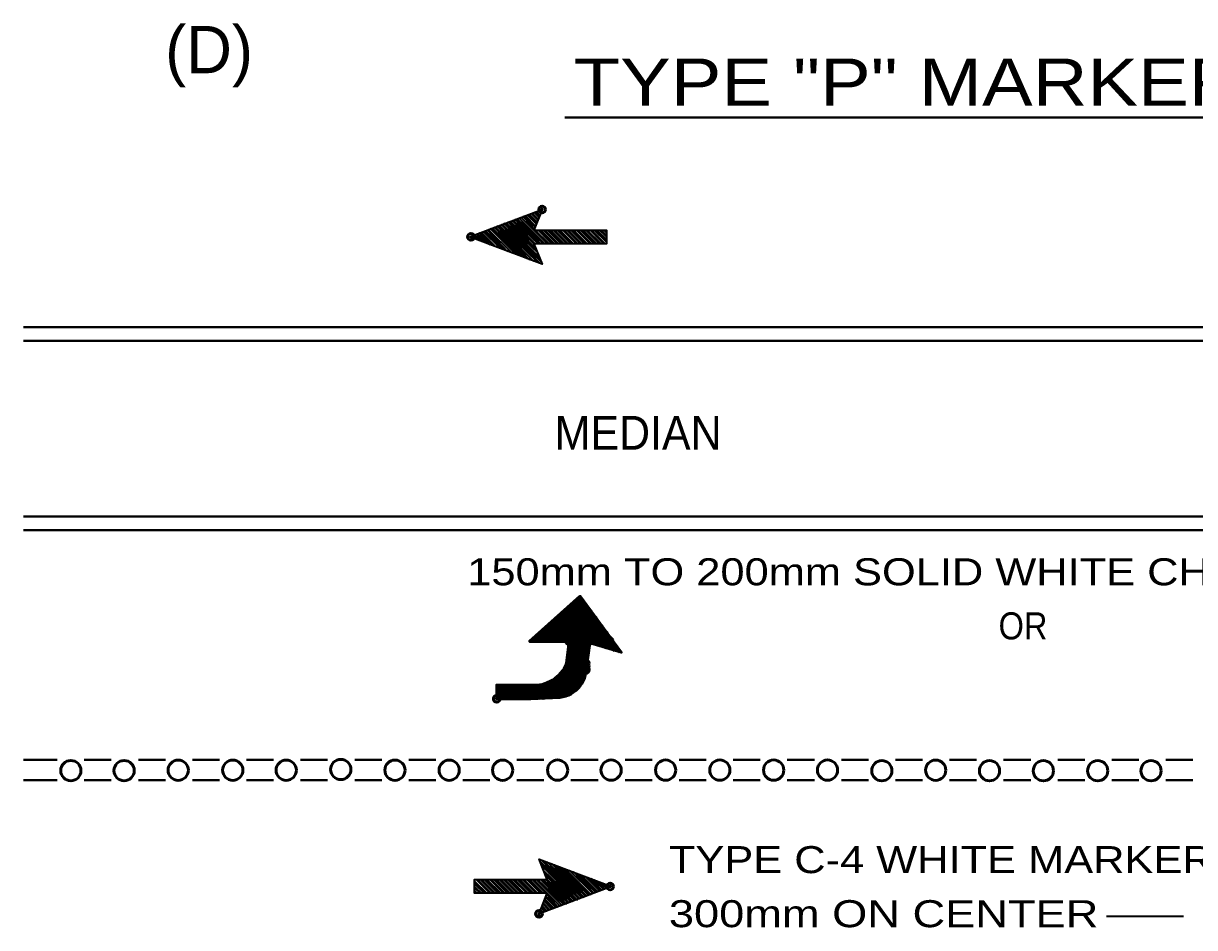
# Model space of a CAD drawing. Extents: x -96 to 617, y -65 to 388.
# Drawn here: x 335.8 to 422.4, y 246.3 to 313.3 of the extents above; entities that cross this region are included whole.
import ezdxf
from ezdxf.enums import TextEntityAlignment as Align

# ---------------------------------------------------------------- set-up
doc = ezdxf.new("R2010")
doc.units = 0
doc.header["$PDMODE"] = 32
doc.header["$PDSIZE"] = 0.5
doc.layers.add('1', color=7, linetype='Continuous', lineweight=53)

msp = doc.modelspace()

# ---------------------------------------------------------------- linework, layer by layer
at = {"layer": '1', "lineweight": 40}
for p, q in [((375.796, 306.296), (431.03, 306.296)), ((335.757, 290.765), (426.757, 290.765)), ((335.757, 289.765), (426.757, 289.765)), ((335.757, 276.765), (426.757, 276.765)), ((335.757, 275.765), (426.757, 275.765)), ((335.757, 258.765), (338.257, 258.765)), ((340.257, 258.765), (342.257, 258.765)), ((344.257, 258.765), (346.257, 258.765)), ((348.257, 258.765), (350.257, 258.765)), ((352.257, 258.765), (354.257, 258.765)), ((356.257, 258.765), (358.257, 258.765)), ((360.257, 258.765), (362.257, 258.765)), ((364.257, 258.765), (366.257, 258.765)), ((368.257, 258.765), (370.257, 258.765)), ((372.257, 258.765), (374.257, 258.765)), ((376.257, 258.765), (378.257, 258.765)), ((380.257, 258.765), (382.257, 258.765)), ((384.257, 258.765), (386.257, 258.765)), ((388.257, 258.765), (390.257, 258.765)), ((392.257, 258.765), (394.257, 258.765)), ((396.257, 258.765), (398.257, 258.765)), ((400.257, 258.765), (402.257, 258.765)), ((404.257, 258.765), (406.257, 258.765)), ((408.257, 258.765), (410.257, 258.765)), ((412.257, 258.765), (414.257, 258.765)), ((416.257, 258.765), (418.257, 258.765)), ((420.257, 258.765), (422.257, 258.765)), ((335.757, 257.265), (338.257, 257.265)), ((340.257, 257.265), (342.257, 257.265)), ((344.257, 257.265), (346.257, 257.265)), ((348.257, 257.265), (350.257, 257.265)), ((352.257, 257.265), (354.257, 257.265)), ((356.257, 257.265), (358.257, 257.265)), ((360.257, 257.265), (362.257, 257.265)), ((364.257, 257.265), (366.257, 257.265)), ((368.257, 257.265), (370.257, 257.265)), ((372.257, 257.265), (374.257, 257.265)), ((376.257, 257.265), (378.257, 257.265)), ((380.257, 257.265), (382.257, 257.265)), ((384.257, 257.265), (386.257, 257.265)), ((388.257, 257.265), (390.257, 257.265)), ((392.257, 257.265), (394.257, 257.265)), ((396.257, 257.265), (398.257, 257.265)), ((400.257, 257.265), (402.257, 257.265)), ((404.257, 257.265), (406.257, 257.265)), ((408.257, 257.265), (410.257, 257.265)), ((412.257, 257.265), (414.257, 257.265)), ((416.257, 257.265), (418.257, 257.265)), ((420.257, 257.265), (422.257, 257.265))]:
    msp.add_line(p, q, dxfattribs=at)
at = {"layer": '1', "lineweight": 35}
for p, q in [((374.326, 296.954), (372.402, 298.878)), ((374.528, 296.954), (372.605, 298.878)), ((373.516, 298.068), (372.706, 298.979)), ((373.617, 298.169), (372.807, 298.979)), ((373.617, 298.271), (372.908, 298.979)), ((373.718, 298.372), (373.01, 299.081)), ((373.718, 298.473), (373.111, 299.081)), ((373.718, 298.574), (373.212, 299.081)), ((373.82, 298.676), (373.313, 299.182)), ((373.82, 298.777), (373.415, 299.182)), ((373.921, 298.878), (373.516, 299.283)), ((373.921, 298.979), (373.617, 299.283)), ((373.921, 299.081), (373.718, 299.283)), ((374.022, 299.182), (373.82, 299.384)), ((374.022, 299.283), (373.921, 299.384)), ((374.123, 299.384), (374.022, 299.486)), ((372.098, 296.246), (370.276, 298.068)), ((372.301, 296.144), (370.377, 298.068)), ((372.605, 296.043), (370.478, 298.068)), ((372.807, 295.942), (370.58, 298.169)), ((373.01, 295.841), (370.681, 298.169)), ((373.212, 295.739), (370.782, 298.271)), ((373.516, 295.638), (370.883, 298.271)), ((373.718, 295.638), (370.985, 298.271)), ((373.921, 295.537), (371.086, 298.372)), ((374.123, 295.537), (371.187, 298.372)), ((374.022, 295.739), (371.288, 298.473)), ((373.921, 295.942), (371.39, 298.473)), ((373.82, 296.246), (371.491, 298.473)), ((373.718, 296.448), (371.592, 298.574)), ((373.617, 296.651), (371.693, 298.574)), ((373.516, 296.954), (371.795, 298.574)), ((373.617, 296.954), (371.896, 298.676)), ((373.82, 296.954), (371.997, 298.676)), ((373.921, 296.954), (372.098, 298.777)), ((374.022, 296.954), (372.2, 298.777)), ((374.225, 296.954), (372.301, 298.777)), ((369.162, 297.359), (368.96, 297.562)), ((369.365, 297.258), (369.061, 297.562)), ((369.567, 297.157), (369.162, 297.562)), ((369.77, 297.056), (369.263, 297.663)), ((370.073, 296.954), (369.365, 297.663)), ((370.276, 296.853), (369.466, 297.764)), ((370.478, 296.853), (369.567, 297.764)), ((370.681, 296.752), (369.668, 297.764)), ((370.985, 296.651), (369.77, 297.866)), ((371.187, 296.549), (369.871, 297.866)), ((371.39, 296.448), (369.972, 297.866)), ((371.592, 296.347), (370.073, 297.967)), ((371.896, 296.246), (370.175, 297.967)), ((374.63, 296.954), (373.617, 297.967)), ((374.832, 296.954), (373.82, 297.967)), ((374.933, 296.954), (373.921, 297.967)), ((375.035, 296.954), (374.022, 297.967)), ((375.237, 296.954), (374.225, 297.967)), ((375.338, 296.954), (374.326, 297.967)), ((375.541, 296.954), (374.528, 297.967)), ((375.642, 296.954), (374.63, 297.967)), ((375.743, 296.954), (374.731, 297.967)), ((375.946, 296.954), (374.933, 297.967)), ((376.047, 296.954), (375.035, 297.967)), ((376.25, 296.954), (375.237, 297.967)), ((376.351, 296.954), (375.338, 297.967)), ((376.452, 296.954), (375.44, 297.967)), ((376.655, 296.954), (375.642, 297.967)), ((376.756, 296.954), (375.743, 297.967)), ((376.958, 296.954), (375.946, 297.967)), ((377.06, 296.954), (376.047, 297.967)), ((377.262, 296.954), (376.25, 297.967)), ((377.363, 296.954), (376.351, 297.967)), ((377.465, 296.954), (376.452, 297.967)), ((377.667, 296.954), (376.655, 297.967)), ((377.768, 296.954), (376.756, 297.967)), ((377.971, 296.954), (376.958, 297.967)), ((378.072, 296.954), (377.06, 297.967)), ((378.173, 296.954), (377.161, 297.967)), ((378.376, 296.954), (377.363, 297.967)), ((378.477, 296.954), (377.465, 297.967)), ((378.68, 296.954), (377.667, 297.967)), ((378.781, 296.954), (377.768, 297.967)), ((378.882, 297.056), (377.971, 297.967)), ((378.882, 297.157), (378.072, 297.967)), ((378.882, 297.258), (378.173, 297.967)), ((378.882, 297.461), (378.376, 297.967)), ((378.882, 297.562), (378.477, 297.967)), ((378.882, 297.764), (378.68, 297.967)), ((378.882, 297.866), (378.781, 297.967)), ((378.882, 296.954), (373.516, 296.954)), ((373.891, 251.313), (376.827, 248.478)), ((374.093, 251.313), (376.928, 248.478)), ((374.296, 251.212), (377.03, 248.58)), ((374.498, 251.212), (377.131, 248.58)), ((373.992, 251.111), (376.726, 248.377)), ((374.093, 250.908), (376.625, 248.377)), ((374.195, 250.605), (376.523, 248.377)), ((374.296, 250.402), (376.422, 248.276)), ((374.802, 251.111), (377.232, 248.58)), ((375.005, 251.01), (377.333, 248.681)), ((375.207, 250.908), (377.435, 248.681)), ((375.41, 250.807), (377.536, 248.782)), ((375.713, 250.706), (377.637, 248.782)), ((375.916, 250.605), (377.738, 248.782)), ((376.118, 250.605), (377.84, 248.883)), ((376.422, 250.503), (377.941, 248.883)), ((376.625, 250.402), (378.042, 248.985)), ((369.132, 249.896), (374.498, 249.896)), ((369.132, 249.795), (370.043, 248.883)), ((369.132, 249.693), (369.942, 248.883)), ((369.132, 249.592), (369.841, 248.883)), ((369.233, 249.896), (370.246, 248.883)), ((369.335, 249.896), (370.347, 248.883)), ((369.537, 249.896), (370.55, 248.883)), ((369.638, 249.896), (370.651, 248.883)), ((369.841, 249.896), (370.853, 248.883)), ((369.942, 249.896), (370.955, 248.883)), ((370.043, 249.896), (371.056, 248.883)), ((370.246, 249.896), (371.258, 248.883)), ((370.347, 249.896), (371.36, 248.883)), ((370.55, 249.896), (371.562, 248.883)), ((370.651, 249.896), (371.663, 248.883)), ((370.752, 249.896), (371.765, 248.883)), ((370.955, 249.896), (371.967, 248.883)), ((371.056, 249.896), (372.068, 248.883)), ((371.258, 249.896), (372.271, 248.883)), ((371.36, 249.896), (372.372, 248.883)), ((371.562, 249.896), (372.575, 248.883)), ((371.663, 249.896), (372.676, 248.883)), ((371.765, 249.896), (372.777, 248.883)), ((371.967, 249.896), (372.98, 248.883)), ((372.068, 249.896), (373.081, 248.883)), ((372.271, 249.896), (373.283, 248.883)), ((372.372, 249.896), (373.385, 248.883)), ((372.473, 249.896), (373.486, 248.883)), ((372.676, 249.896), (373.688, 248.883)), ((372.777, 249.896), (373.79, 248.883)), ((372.98, 249.896), (373.992, 248.883)), ((373.081, 249.896), (374.093, 248.883)), ((373.182, 249.896), (374.195, 248.883)), ((373.385, 249.896), (374.397, 248.883)), ((373.486, 249.896), (375.41, 247.972)), ((373.688, 249.896), (375.612, 247.972)), ((373.79, 249.896), (375.713, 248.073)), ((373.992, 249.896), (375.815, 248.073)), ((374.093, 249.896), (375.916, 248.073)), ((374.195, 249.896), (376.017, 248.175)), ((374.397, 250.2), (376.321, 248.276)), ((374.397, 249.896), (376.118, 248.175)), ((374.498, 249.896), (376.22, 248.276)), ((376.827, 250.301), (378.143, 248.985)), ((377.03, 250.2), (378.245, 248.985)), ((377.333, 250.098), (378.346, 249.086)), ((377.536, 249.997), (378.447, 249.086)), ((377.738, 249.997), (378.548, 249.086)), ((377.941, 249.896), (378.65, 249.187)), ((378.245, 249.795), (378.751, 249.187)), ((378.447, 249.693), (378.852, 249.288)), ((378.65, 249.592), (378.953, 249.288)), ((378.852, 249.491), (379.055, 249.288)), ((369.132, 249.39), (369.638, 248.883)), ((369.132, 249.288), (369.537, 248.883)), ((369.132, 249.086), (369.335, 248.883)), ((369.132, 248.985), (369.233, 248.883)), ((374.397, 248.681), (375.207, 247.871)), ((374.498, 248.782), (375.308, 247.871)), ((374.093, 247.972), (374.498, 247.567)), ((374.093, 247.871), (374.397, 247.567)), ((374.093, 247.77), (374.296, 247.567)), ((374.195, 248.175), (374.701, 247.668)), ((374.195, 248.073), (374.6, 247.668)), ((374.296, 248.478), (375.005, 247.77)), ((374.296, 248.377), (374.903, 247.77)), ((374.296, 248.276), (374.802, 247.77)), ((374.397, 248.58), (375.106, 247.871)), ((373.891, 247.466), (373.992, 247.365)), ((373.992, 247.668), (374.195, 247.466)), ((373.992, 247.567), (374.093, 247.466)), ((415.865, 247.193), (421.564, 247.193))]:
    msp.add_line(p, q, dxfattribs=at)
at = {"layer": '1'}
for p, q in [((376.231, 270.261), (379.673, 266.818)), ((376.332, 270.362), (379.876, 266.717)), ((376.433, 270.464), (379.369, 267.628)), ((376.433, 270.362), (379.673, 267.021)), ((376.534, 270.565), (378.964, 268.135)), ((376.636, 270.565), (378.559, 268.641)), ((376.737, 270.767), (377.749, 269.755)), ((376.737, 270.666), (378.154, 269.248)), ((376.838, 270.767), (377.344, 270.261)), ((375.319, 269.451), (377.648, 267.122)), ((375.421, 269.552), (377.648, 267.325)), ((375.522, 269.654), (377.851, 267.325)), ((375.522, 269.552), (377.648, 267.426)), ((375.623, 269.755), (378.053, 267.325)), ((375.724, 269.755), (378.256, 267.224)), ((375.826, 269.957), (378.661, 267.122)), ((375.826, 269.856), (378.458, 267.224)), ((375.927, 269.957), (378.863, 267.021)), ((376.028, 270.058), (379.066, 267.021)), ((376.129, 270.16), (379.471, 266.818)), ((376.129, 270.16), (379.268, 266.92)), ((374.307, 268.54), (375.421, 267.527)), ((374.307, 268.54), (375.218, 267.527)), ((374.408, 268.641), (375.522, 267.527)), ((374.509, 268.742), (375.724, 267.527)), ((374.611, 268.844), (375.927, 267.527)), ((374.611, 268.742), (375.826, 267.527)), ((374.712, 268.945), (376.129, 267.527)), ((374.813, 268.945), (377.446, 266.312)), ((374.914, 269.147), (377.547, 266.515)), ((374.914, 269.046), (377.547, 266.413)), ((375.016, 269.147), (377.547, 266.717)), ((375.117, 269.248), (377.547, 266.818)), ((375.218, 269.35), (377.547, 267.021)), ((375.218, 269.35), (377.547, 266.92)), ((373.396, 267.73), (373.497, 267.527)), ((373.497, 267.831), (373.801, 267.527)), ((373.497, 267.73), (373.699, 267.527)), ((373.598, 267.932), (374.003, 267.527)), ((373.699, 267.932), (374.104, 267.527)), ((373.801, 268.135), (374.408, 267.527)), ((373.801, 268.034), (374.206, 267.527)), ((373.902, 268.135), (374.509, 267.527)), ((374.003, 268.236), (374.712, 267.527)), ((374.104, 268.337), (375.016, 267.527)), ((374.104, 268.337), (374.813, 267.527)), ((374.206, 268.438), (375.117, 267.527)), ((373.193, 267.527), (373.294, 267.527)), ((373.294, 267.628), (373.396, 267.527)), ((376.028, 267.021), (377.344, 265.705)), ((376.129, 267.527), (377.446, 266.211)), ((376.129, 267.426), (377.446, 266.008)), ((376.129, 267.224), (377.446, 265.907)), ((376.129, 267.122), (377.344, 265.907)), ((375.927, 266.211), (377.243, 264.895)), ((375.927, 266.11), (377.243, 264.793)), ((375.927, 266.008), (377.243, 264.692)), ((376.028, 266.717), (377.344, 265.401)), ((376.028, 266.616), (377.344, 265.3)), ((376.028, 266.515), (377.344, 265.198)), ((376.028, 266.413), (377.344, 264.996)), ((375.421, 265.097), (376.636, 263.882)), ((375.522, 265.198), (376.737, 263.983)), ((375.522, 265.198), (376.636, 263.983)), ((375.623, 265.401), (376.838, 264.186)), ((375.623, 265.3), (376.838, 264.085)), ((375.724, 265.603), (377.041, 264.388)), ((375.724, 265.502), (376.939, 264.287)), ((375.826, 265.806), (377.142, 264.49)), ((375.826, 265.705), (377.041, 264.388)), ((375.927, 265.907), (377.142, 264.591)), ((377.344, 265.907), (377.446, 265.806)), ((377.344, 265.705), (377.446, 265.705)), ((370.763, 264.287), (371.776, 263.275)), ((370.864, 264.287), (371.877, 263.275)), ((371.067, 264.287), (372.079, 263.275)), ((371.168, 264.287), (372.181, 263.275)), ((371.371, 264.287), (372.383, 263.275)), ((371.472, 264.287), (372.484, 263.275)), ((371.573, 264.287), (372.586, 263.275)), ((371.776, 264.287), (372.788, 263.275)), ((371.877, 264.287), (372.889, 263.275)), ((372.079, 264.287), (373.092, 263.275)), ((372.181, 264.287), (373.193, 263.275)), ((372.383, 264.287), (373.294, 263.275)), ((372.484, 264.287), (373.497, 263.275)), ((372.586, 264.287), (373.598, 263.275)), ((372.788, 264.287), (373.801, 263.275)), ((372.889, 264.287), (373.902, 263.275)), ((373.092, 264.287), (374.003, 263.275)), ((373.193, 264.287), (374.206, 263.275)), ((373.294, 264.287), (374.307, 263.275)), ((373.497, 264.287), (374.408, 263.376)), ((373.598, 264.287), (374.611, 263.376)), ((373.801, 264.287), (374.712, 263.376)), ((373.902, 264.287), (374.813, 263.376)), ((374.003, 264.287), (375.016, 263.376)), ((374.104, 264.388), (375.117, 263.376)), ((374.206, 264.388), (375.218, 263.376)), ((374.408, 264.388), (375.421, 263.376)), ((374.509, 264.49), (375.522, 263.376)), ((374.611, 264.49), (375.724, 263.477)), ((374.611, 264.49), (375.623, 263.376)), ((374.712, 264.591), (375.826, 263.477)), ((374.813, 264.591), (375.927, 263.477)), ((374.914, 264.692), (376.028, 263.579)), ((375.016, 264.793), (376.129, 263.579)), ((375.117, 264.793), (376.231, 263.68)), ((375.218, 264.895), (376.433, 263.781)), ((375.218, 264.895), (376.332, 263.68)), ((375.319, 264.996), (376.534, 263.781)), ((370.763, 264.186), (371.674, 263.275)), ((370.763, 263.983), (371.472, 263.275)), ((370.763, 263.882), (371.371, 263.275)), ((370.763, 263.68), (371.168, 263.275)), ((370.763, 263.579), (371.067, 263.275)), ((370.763, 263.376), (370.864, 263.275))]:
    msp.add_line(p, q, dxfattribs=at)
at = {"layer": '1', "lineweight": 35}
for points in [[(368.757, 297.461), (374.123, 299.486), (373.516, 297.967), (378.882, 297.967), (378.882, 296.954), (373.516, 296.954), (374.123, 295.436)], [(379.257, 249.39), (373.891, 247.365), (374.498, 248.883), (369.132, 248.883), (369.132, 249.896), (374.498, 249.896), (373.891, 251.415)]]:
    msp.add_lwpolyline(points, close=True, dxfattribs=at)
for points in [[(373.516, 297.967), (378.882, 297.967), (378.882, 296.954)], [(374.498, 248.883), (369.132, 248.883), (369.132, 249.896)]]:
    msp.add_lwpolyline(points, dxfattribs=at)
at = {"layer": '1'}
for points in [[(375.927, 265.907), (376.129, 267.527), (373.193, 267.527), (376.939, 270.868), (376.939, 270.767)], [(376.939, 270.868), (379.977, 266.717), (377.648, 267.426), (377.344, 265.3)], [(376.028, 266.92), (377.344, 265.603), (377.344, 265.502)], [(375.421, 263.376), (373.294, 263.275), (370.763, 263.275), (370.763, 264.287), (373.294, 264.287)]]:
    msp.add_lwpolyline(points, dxfattribs=at)
for centre in [(339.265, 257.962), (343.205, 257.962), (347.206, 257.994), (351.241, 257.994), (355.196, 257.994), (359.231, 258.048), (363.239, 257.994), (367.248, 257.994), (371.202, 257.994), (375.267, 258.003), (379.222, 258.003), (383.257, 258.003), (387.265, 258.003), (391.247, 258.003), (395.229, 258.003), (399.248, 257.955), (403.23, 257.992), (407.212, 257.955), (411.193, 257.955), (415.212, 257.955), (419.157, 257.955)]:
    msp.add_circle(centre, 0.75, dxfattribs=at)
for centre, radius, start, end in [((373.536, 266.843), 2.567, 264.58762, 338.62739), ((375.189, 265.549), 2.185, 276.08048, 9.44985)]:
    msp.add_arc(centre, radius, start, end, dxfattribs=at)
for p in [(374.123, 299.486), (368.858, 297.461), (376.129, 267.527), (377.344, 265.907), (377.344, 265.705), (377.344, 265.502), (377.344, 265.401), (370.763, 263.275), (379.156, 249.39), (373.891, 247.365)]:
    msp.add_point(p, dxfattribs=at)

# ---------------------------------------------------------------- texts
msp.add_text('(D)', height=3.5, dxfattribs=at).set_placement((349.489, 309.568), align=Align.CENTER)
for s, height, width, p in [('TYPE "P" MARKERS', 3.5, 1.2, (403.107, 307.157)), ('MEDIAN', 2.5, 0.95, (381.222, 281.712)), ('150mm TO 200mm SOLID WHITE CHANNELIZING LINE', 2, 1.2, (409.688, 271.675)), ('OR', 2, 0.9, (409.688, 267.675))]:
    msp.add_text(s, height=height, dxfattribs=dict(at, width=width)).set_placement(p, align=Align.CENTER)
for s, width, p in [('TYPE C-4 WHITE MARKERS', 1.2, (383.496, 250.376)), ('300mm ON CENTER', 1.25, (383.496, 246.376))]:
    msp.add_text(s, height=2, dxfattribs=dict(at, width=width)).set_placement(p)

doc.saveas('drawing.dxf')
